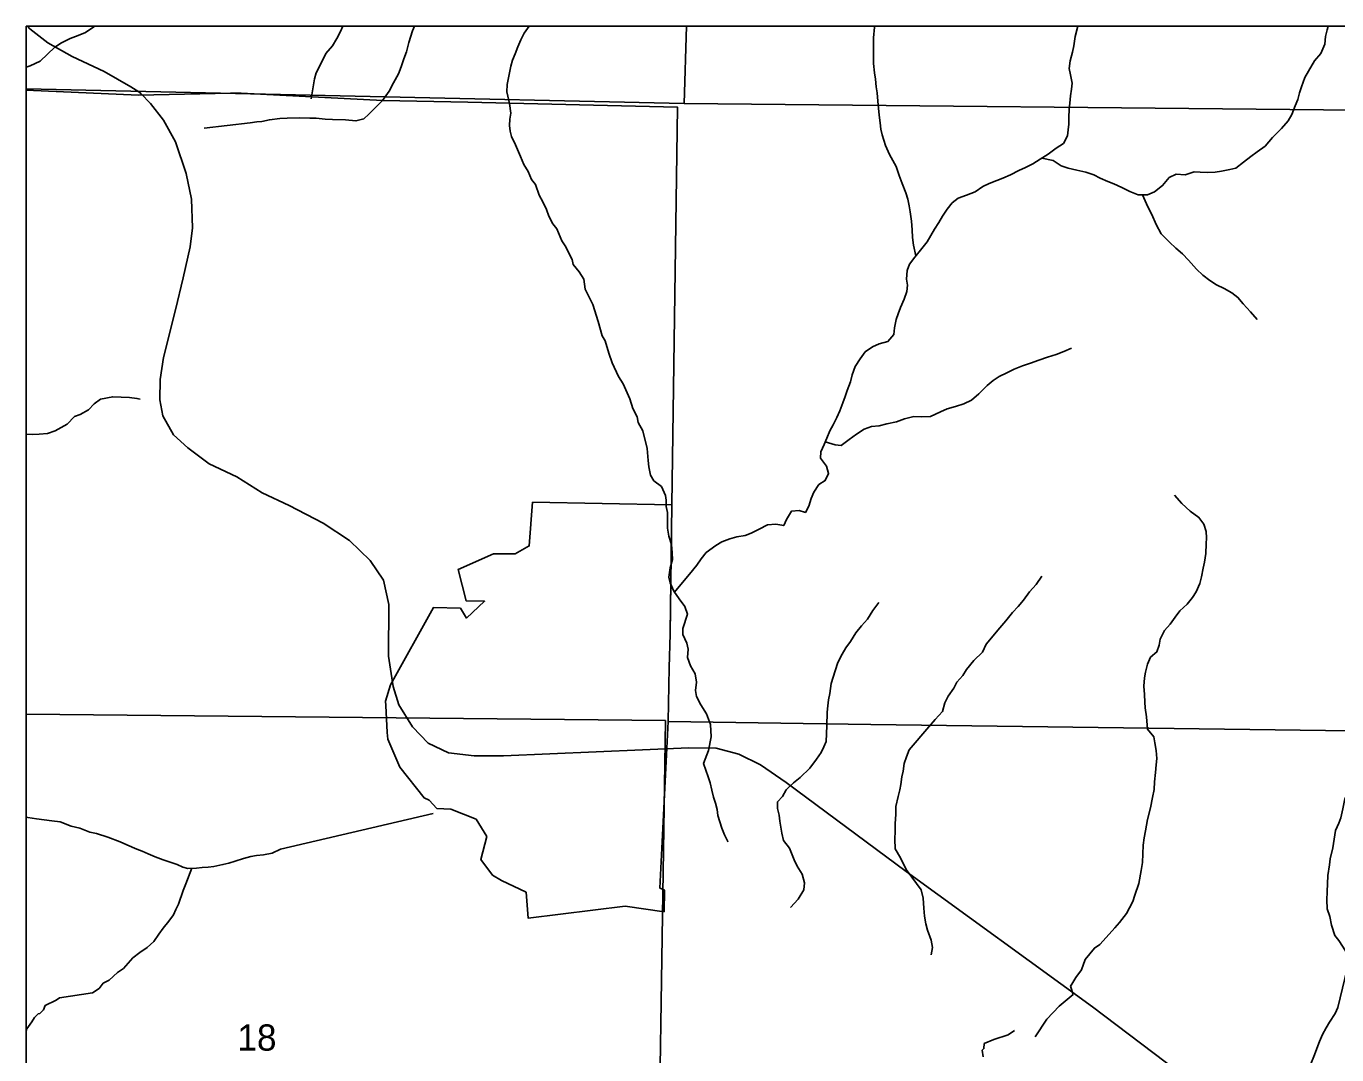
# Model space of a CAD drawing. Extents: x -10 to 158, y 8 to 33.
# Drawn here: x -9.791 to -7.704, y 21.18 to 22.818 of the extents above; entities that cross this region are included whole.
import ezdxf

# ---------------------------------------------------------------- set-up
doc = ezdxf.new("R2010")
doc.units = 0
for name, color, linetype in [('GM_X_Corporation', 7, 'Continuous'), ('GM_X_Minor_River', 7, 'Continuous'), ('GM_X_Rail_Line', 7, 'Continuous'), ('GM_X_Section_Text', 7, 'Continuous')]:
    doc.layers.add(name, color=color, linetype=linetype)

msp = doc.modelspace()

# ---------------------------------------------------------------- linework, layer by layer
at = {"layer": 'GM_X_Corporation'}
for points in [[(-2.9914, 22.8183), (-9.7914, 22.8183), (-9.7914, 22.7162), (-9.6128, 22.7087), (-9.4661, 22.7117), (-9.4489, 22.7118), (-9.2233, 22.7001), (-9.0882, 22.6971), (-8.7542, 22.6895), (-8.7629, 22.056), (-8.7657, 21.852), (-8.7657, 21.8499), (-8.7672, 21.7965), (-8.7692, 21.7106), (-8.4462, 21.7057), (-7.2795, 21.6904)], [(-3.5803, 22.8183), (-9.7914, 22.8183), (-9.7914, 22.7162), (-9.6128, 22.7087), (-9.4661, 22.7117), (-9.4489, 22.7118), (-9.2233, 22.7001), (-9.0882, 22.6971), (-8.7542, 22.6895), (-8.7629, 22.056), (-8.7657, 21.852), (-8.7657, 21.8499), (-8.7672, 21.7965), (-8.7692, 21.7106), (-8.4462, 21.7057), (-7.2795, 21.6904)], [(-7.2795, 21.6904), (-8.4462, 21.7057), (-8.7692, 21.7106), (-8.7672, 21.7965), (-8.7657, 21.8499), (-8.7657, 21.852), (-8.7629, 22.056), (-8.7542, 22.6895), (-9.0882, 22.6971), (-9.2233, 22.7001), (-9.4489, 22.7118), (-9.4661, 22.7117), (-9.6128, 22.7087), (-9.7914, 22.7162), (-9.7914, 16.0183)], [(-7.2795, 21.6904), (-8.4462, 21.7057), (-8.7692, 21.7106), (-8.7672, 21.7965), (-8.7657, 21.8499), (-8.7657, 21.852), (-8.7629, 22.056), (-8.7542, 22.6895), (-9.0882, 22.6971), (-9.2233, 22.7001), (-9.4489, 22.7118), (-9.4661, 22.7117), (-9.6128, 22.7087), (-9.7914, 22.7162), (-9.7914, 18.392)]]:
    msp.add_lwpolyline(points, dxfattribs=at)
for points in [[(-8.74, 22.8183), (-9.7914, 22.8183), (-9.7914, 22.7186), (-8.7435, 22.6953)], [(-7.6698, 22.8183), (-8.74, 22.8183), (-8.7435, 22.6953), (-7.6718, 22.6845)], [(-8.7692, 21.7106), (-8.7821, 21.4452), (-8.778, 21.4433), (-8.7748, 21.4417), (-8.7754, 21.4075), (-8.8374, 21.4166), (-8.9919, 21.3972), (-8.9953, 21.4385), (-9.0345, 21.4574), (-9.0486, 21.4657), (-9.0672, 21.4909), (-9.0579, 21.5274), (-9.0748, 21.555), (-9.1149, 21.5711), (-9.1372, 21.572), (-9.1497, 21.5854), (-9.1577, 21.5889), (-9.1961, 21.638), (-9.2157, 21.6826), (-9.2163, 21.6931), (-9.2187, 21.736), (-9.2193, 21.7432), (-9.2113, 21.7691), (-9.1426, 21.8922), (-9.0998, 21.8913), (-9.09, 21.8752), (-9.0615, 21.9022), (-9.0909, 21.9029), (-9.1033, 21.9528), (-9.0474, 21.9778), (-9.0124, 21.9778), (-8.9901, 21.9903), (-8.9848, 22.0598), (-8.7629, 22.056), (-8.7657, 21.8499), (-8.7672, 21.7965)], [(-9.7914, 21.7221), (-9.7914, 20.728), (-8.7888, 20.7117), (-8.7733, 21.712)]]:
    msp.add_lwpolyline(points, close=True, dxfattribs=at)
at = {"layer": 'GM_X_Minor_River'}
for points in [[(-9.6822, 22.8183), (-9.6835, 22.8173), (-9.6971, 22.8082), (-9.7089, 22.8035), (-9.7214, 22.7985), (-9.7354, 22.792), (-9.7456, 22.7847), (-9.7573, 22.774), (-9.769, 22.7626), (-9.7849, 22.7552), (-9.7914, 22.7532)], [(-9.3373, 22.7024), (-9.3351, 22.7187), (-9.3321, 22.7343), (-9.3295, 22.7438), (-9.3228, 22.7575), (-9.3142, 22.7746), (-9.3036, 22.7868), (-9.2965, 22.7986), (-9.2909, 22.8097), (-9.2872, 22.8183)], [(-9.2241, 22.6999), (-9.2132, 22.7146), (-9.2064, 22.7283), (-9.1985, 22.7424), (-9.1941, 22.7538), (-9.19, 22.7663), (-9.1855, 22.7777), (-9.1818, 22.7922), (-9.1762, 22.8112), (-9.1732, 22.8183)], [(-9.0217, 22.6953), (-9.026, 22.7139), (-9.0253, 22.7257), (-9.0224, 22.7413), (-9.0198, 22.7546), (-9.0168, 22.7641), (-9.0127, 22.7743), (-9.0082, 22.7854), (-9.0034, 22.7968), (-8.9985, 22.807), (-8.9903, 22.8183)], [(-8.7587, 21.9164), (-8.7459, 21.9322), (-8.735, 21.9455), (-8.7233, 21.9596), (-8.7166, 21.9695), (-8.7083, 21.9798), (-8.6932, 21.9909), (-8.6833, 21.9967), (-8.6708, 22.0017), (-8.6598, 22.0048), (-8.6462, 22.0071), (-8.6367, 22.0106), (-8.6238, 22.0168), (-8.6106, 22.0237), (-8.5973, 22.0249), (-8.5848, 22.0227), (-8.5807, 22.0322), (-8.5728, 22.0456), (-8.5606, 22.0468), (-8.5504, 22.0438), (-8.5451, 22.0537), (-8.5414, 22.0659), (-8.5369, 22.0757), (-8.529, 22.0879), (-8.5188, 22.0945), (-8.5136, 22.1059), (-8.517, 22.1176), (-8.5266, 22.1301), (-8.5259, 22.1403), (-8.5207, 22.1517), (-8.5162, 22.162), (-8.5113, 22.1734), (-8.5061, 22.1833), (-8.5005, 22.1951), (-8.4956, 22.2054), (-8.4908, 22.2183), (-8.487, 22.2285), (-8.4837, 22.2381), (-8.4788, 22.2517), (-8.4759, 22.2628), (-8.471, 22.2764), (-8.4631, 22.2886), (-8.4552, 22.2993), (-8.4435, 22.3077), (-8.4329, 22.312), (-8.4189, 22.3158), (-8.4098, 22.3273), (-8.4084, 22.3375), (-8.4058, 22.3508), (-8.4028, 22.3603), (-8.3991, 22.3702), (-8.3931, 22.3835), (-8.389, 22.3957), (-8.388, 22.4059), (-8.3895, 22.4154), (-8.3881, 22.4291), (-8.3848, 22.439), (-8.3761, 22.4504), (-8.3648, 22.4641), (-8.3565, 22.4748), (-8.3505, 22.4847), (-8.3449, 22.495), (-8.3377, 22.5056), (-8.3321, 22.5159), (-8.3246, 22.527), (-8.3167, 22.5369), (-8.3069, 22.5445), (-8.2936, 22.5492), (-8.2803, 22.5546), (-8.2679, 22.563), (-8.258, 22.5676), (-8.2455, 22.5726), (-8.2361, 22.5761), (-8.2236, 22.5815), (-8.2103, 22.5884), (-8.1997, 22.593), (-8.1884, 22.5992), (-8.1763, 22.6065), (-8.1638, 22.6145), (-8.1509, 22.6241), (-8.1396, 22.6317), (-8.1332, 22.6435), (-8.1318, 22.653), (-8.1307, 22.6625), (-8.1311, 22.6735), (-8.1301, 22.6856), (-8.1294, 22.6955), (-8.1283, 22.7073), (-8.1265, 22.7179), (-8.1254, 22.7278), (-8.1282, 22.741), (-8.1301, 22.7509), (-8.1287, 22.7634), (-8.125, 22.7767), (-8.1228, 22.7873), (-8.121, 22.8021), (-8.1173, 22.8162), (-8.1166, 22.8183)], [(-8.3743, 22.4526), (-8.3785, 22.4693), (-8.3801, 22.4819), (-8.3806, 22.494), (-8.3814, 22.5076), (-8.3834, 22.5224), (-8.3854, 22.5323), (-8.3873, 22.5425), (-8.3904, 22.5527), (-8.3962, 22.5678), (-8.4009, 22.5807), (-8.4059, 22.5947), (-8.4163, 22.614), (-8.4228, 22.6284), (-8.4283, 22.645), (-8.4302, 22.6545), (-8.4314, 22.6643), (-8.433, 22.6768), (-8.4342, 22.6878), (-8.4351, 22.6988), (-8.4359, 22.7121), (-8.4375, 22.7216), (-8.4387, 22.7341), (-8.4403, 22.7439), (-8.4419, 22.7587), (-8.4422, 22.7997), (-8.4404, 22.8168), (-8.4402, 22.8183)], [(-8.1738, 22.608), (-8.1557, 22.6043), (-8.1432, 22.596), (-8.1317, 22.5923), (-8.1181, 22.589), (-8.1036, 22.5857), (-8.091, 22.5816), (-8.0808, 22.576), (-8.069, 22.5711), (-8.0591, 22.5674), (-8.0465, 22.5614), (-8.0335, 22.5547), (-8.0202, 22.5494), (-8.0058, 22.5495), (-7.9944, 22.5542), (-7.9816, 22.5645), (-7.971, 22.5774), (-7.9597, 22.5828), (-7.9456, 22.5814), (-7.9312, 22.5864), (-7.9217, 22.5857), (-7.9103, 22.585), (-7.8978, 22.5859), (-7.8876, 22.5875), (-7.8747, 22.5898), (-7.8648, 22.5922), (-7.8527, 22.6017), (-7.841, 22.6105), (-7.8308, 22.6182), (-7.8183, 22.6274), (-7.8063, 22.6411), (-7.792, 22.6556), (-7.7818, 22.6674), (-7.7758, 22.6777), (-7.7702, 22.6914), (-7.7664, 22.7017), (-7.7635, 22.7123), (-7.7601, 22.7218), (-7.7549, 22.7366), (-7.7493, 22.7469), (-7.7395, 22.7633), (-7.7293, 22.7747), (-7.7234, 22.7899), (-7.7223, 22.8021), (-7.7197, 22.8123), (-7.718, 22.8183)], [(-9.2241, 22.6999), (-9.2457, 22.678), (-9.2539, 22.6707), (-9.2664, 22.6675), (-9.2828, 22.6691), (-9.3034, 22.6696), (-9.3152, 22.6701), (-9.3296, 22.6718), (-9.3395, 22.672), (-9.3555, 22.6722), (-9.3756, 22.6719), (-9.3874, 22.6713), (-9.4041, 22.6692), (-9.4159, 22.6667), (-9.4242, 22.6658), (-9.4345, 22.6645), (-9.5079, 22.656)], [(-8.773, 22.0706), (-8.7796, 22.0848), (-8.7919, 22.0941), (-8.7969, 22.1032), (-8.7998, 22.1164), (-8.8007, 22.1263), (-8.8025, 22.1456), (-8.8094, 22.1736), (-8.8168, 22.1868), (-8.8185, 22.1959), (-8.8255, 22.209), (-8.8303, 22.2249), (-8.8405, 22.2487), (-8.8479, 22.2603), (-8.8581, 22.2822), (-8.8637, 22.2973), (-8.8693, 22.317), (-8.874, 22.3252), (-8.8804, 22.3479), (-8.8891, 22.3748), (-8.9013, 22.3996), (-8.9034, 22.4155), (-8.9108, 22.4268), (-8.9205, 22.4384), (-8.9221, 22.4468), (-8.9331, 22.4682), (-8.9382, 22.4765), (-8.9464, 22.4954), (-8.9526, 22.5036), (-8.9589, 22.5157), (-8.9629, 22.5263), (-8.9684, 22.5387), (-8.9742, 22.5489), (-8.9802, 22.5659), (-8.9864, 22.5741), (-8.9919, 22.5869), (-8.9989, 22.5982), (-9.004, 22.6107), (-9.0119, 22.6292), (-9.0186, 22.6427), (-9.0206, 22.6511), (-9.0215, 22.6602), (-9.0212, 22.6704), (-9.0195, 22.6799), (-9.0217, 22.6953)], [(-8.0134, 22.5495), (-8.0049, 22.5306), (-7.9987, 22.5181), (-7.9918, 22.5022), (-7.9837, 22.4875), (-7.9704, 22.4743), (-7.9604, 22.4649), (-7.9497, 22.4555), (-7.9402, 22.4453), (-7.9275, 22.4313), (-7.9176, 22.4219), (-7.9062, 22.4132), (-7.8959, 22.4061), (-7.8837, 22.4005), (-7.8711, 22.3934), (-7.8616, 22.3862), (-7.8531, 22.376), (-7.8413, 22.3632), (-7.831, 22.3512)], [(-8.5189, 22.1559), (-8.5032, 22.1511), (-8.4937, 22.1504), (-8.4809, 22.1596), (-8.4688, 22.1684), (-8.4567, 22.1764), (-8.4453, 22.1803), (-8.4332, 22.1815), (-8.4207, 22.1846), (-8.4055, 22.1881), (-8.3926, 22.1928), (-8.3775, 22.1963), (-8.3657, 22.196), (-8.3513, 22.1964), (-8.335, 22.2041), (-8.3248, 22.2087), (-8.3115, 22.2122), (-8.2979, 22.2165), (-8.2857, 22.2227), (-8.274, 22.2326), (-8.2612, 22.246), (-8.2514, 22.2536), (-8.2416, 22.2601), (-8.2298, 22.2659), (-8.2177, 22.272), (-8.2045, 22.277), (-8.192, 22.2817), (-8.1787, 22.2863), (-8.1647, 22.291), (-8.1511, 22.2952), (-8.1389, 22.3002), (-8.1264, 22.3056)], [(-9.61, 22.2242), (-9.6151, 22.2252), (-9.6269, 22.2269), (-9.6535, 22.228), (-9.6729, 22.2239), (-9.683, 22.2169), (-9.6924, 22.2069), (-9.7052, 22.1999), (-9.7147, 22.1967), (-9.7263, 22.1844), (-9.7451, 22.1735), (-9.7576, 22.1695), (-9.7705, 22.1681), (-9.7812, 22.168), (-9.7914, 22.1682)], [(-8.7016, 21.7056), (-8.7081, 21.723), (-8.7169, 21.737), (-8.7238, 21.7502), (-8.7254, 21.7601), (-8.7236, 21.773), (-8.726, 21.7866), (-8.7333, 21.7995), (-8.7383, 21.8123), (-8.7372, 21.826), (-8.7392, 21.8355), (-8.7454, 21.8491), (-8.7458, 21.8586), (-8.7384, 21.8814), (-8.7423, 21.8939), (-8.7514, 21.9059), (-8.7599, 21.918), (-8.766, 21.9313), (-8.768, 21.9407), (-8.7658, 21.9552), (-8.7621, 21.9688), (-8.7626, 21.9795), (-8.7638, 21.9927), (-8.7677, 22.0056), (-8.77, 22.0185), (-8.7702, 22.0435), (-8.7722, 22.053), (-8.7722, 22.0632), (-8.773, 22.0706)], [(-8.0055, 21.6981), (-8.0071, 21.7181), (-8.0091, 21.7321), (-8.0096, 21.7416), (-8.0104, 21.7534), (-8.0113, 21.7666), (-8.0102, 21.7799), (-8.0088, 21.7894), (-8.0054, 21.802), (-8.0006, 21.813), (-7.9907, 21.8214), (-7.987, 21.832), (-7.9856, 21.8419), (-7.9784, 21.8556), (-7.9694, 21.8655), (-7.9615, 21.8766), (-7.954, 21.8869), (-7.9426, 21.8976), (-7.934, 21.9079), (-7.9283, 21.9174), (-7.9223, 21.9303), (-7.9198, 21.9409), (-7.9168, 21.9546), (-7.915, 21.9645), (-7.9128, 21.9782), (-7.9121, 21.9937), (-7.9114, 22.0032), (-7.9123, 22.0131), (-7.9158, 22.0252), (-7.9238, 22.0357), (-7.9379, 22.0455), (-7.9509, 22.0579), (-7.9624, 22.0711)], [(-8.3541, 21.7019), (-8.3435, 21.7137), (-8.3322, 21.7266), (-8.3281, 21.7403), (-8.3229, 21.751), (-8.3142, 21.7635), (-8.309, 21.7734), (-8.2999, 21.7837), (-8.2936, 21.7936), (-8.2823, 21.8077), (-8.2683, 21.8211), (-8.2623, 21.834), (-8.254, 21.844), (-8.2438, 21.8562), (-8.231, 21.871), (-8.2205, 21.884), (-8.2114, 21.8939), (-8.2032, 21.9038), (-8.1934, 21.9172), (-8.1828, 21.929), (-8.1738, 21.942)], [(-8.5163, 21.7036), (-8.516, 21.7254), (-8.5149, 21.7353), (-8.5135, 21.7452), (-8.5116, 21.7554), (-8.5094, 21.771), (-8.5061, 21.7812), (-8.5031, 21.7915), (-8.4987, 21.8048), (-8.4919, 21.8177), (-8.4859, 21.828), (-8.4788, 21.8379), (-8.4701, 21.8516), (-8.4611, 21.8631), (-8.4517, 21.8738), (-8.443, 21.8875), (-8.4336, 21.9004)], [(-8.7016, 21.7056), (-8.7004, 21.6859), (-8.705, 21.6645), (-8.7127, 21.6439), (-8.7091, 21.6331), (-8.7055, 21.6226), (-8.7022, 21.6126), (-8.6997, 21.6014), (-8.6969, 21.5902), (-8.6936, 21.5802), (-8.6911, 21.5702), (-8.6897, 21.5606), (-8.6868, 21.5505), (-8.6835, 21.5405), (-8.6795, 21.53), (-8.6739, 21.5195), (-8.6732, 21.5188)], [(-8.5742, 21.4141), (-8.5619, 21.4275), (-8.553, 21.4421), (-8.5517, 21.4535), (-8.5557, 21.4675), (-8.5635, 21.4803), (-8.5682, 21.4901), (-8.576, 21.5085), (-8.5854, 21.5209), (-8.5882, 21.5327), (-8.5911, 21.552), (-8.592, 21.5615), (-8.5948, 21.5717), (-8.595, 21.5823), (-8.5871, 21.5911), (-8.5808, 21.6015), (-8.5696, 21.6127), (-8.5587, 21.6212), (-8.5433, 21.6362), (-8.5329, 21.6508), (-8.5251, 21.6612), (-8.521, 21.6704), (-8.5173, 21.6788), (-8.5163, 21.7036)], [(-8.3503, 21.3387), (-8.3482, 21.3503), (-8.3499, 21.3624), (-8.3559, 21.3779), (-8.3587, 21.3884), (-8.3608, 21.4006), (-8.3617, 21.4131), (-8.3631, 21.429), (-8.3659, 21.4426), (-8.3807, 21.4625), (-8.39, 21.4749), (-8.399, 21.4934), (-8.4076, 21.5077), (-8.4082, 21.5229), (-8.4076, 21.5358), (-8.4074, 21.5475), (-8.4065, 21.5627), (-8.4063, 21.5749), (-8.4027, 21.5913), (-8.4002, 21.6019), (-8.3984, 21.6103), (-8.3967, 21.6225), (-8.3946, 21.6313), (-8.3929, 21.6438), (-8.3892, 21.6545), (-8.3852, 21.6652), (-8.3541, 21.7019)], [(-8.1283, 21.2891), (-8.1261, 21.2921), (-8.1198, 21.3025), (-8.1108, 21.3147), (-8.1046, 21.3315), (-8.0901, 21.3496), (-8.0814, 21.355), (-8.0664, 21.3716), (-8.0574, 21.3816), (-8.05, 21.3905), (-8.0391, 21.4047), (-8.0343, 21.4135), (-8.0292, 21.4238), (-8.0259, 21.4341), (-8.0193, 21.4524), (-8.0158, 21.473), (-8.0133, 21.4859), (-8.0132, 21.4996), (-8.0126, 21.5133), (-8.0109, 21.5254), (-8.0088, 21.5361), (-8.007, 21.5456), (-8.0056, 21.5544), (-8.0006, 21.5731), (-7.9974, 21.5894), (-7.9949, 21.6024), (-7.9943, 21.6142), (-7.993, 21.6294), (-7.9917, 21.6415), (-7.9907, 21.6518), (-7.992, 21.6643), (-7.9941, 21.6768), (-7.9954, 21.6859), (-8.0055, 21.6981)], [(-7.6877, 21.3166), (-7.6874, 21.3219), (-7.6868, 21.3348), (-7.6904, 21.3454), (-7.7009, 21.3616), (-7.7071, 21.3698), (-7.7123, 21.3861), (-7.7151, 21.3997), (-7.7195, 21.4122), (-7.7201, 21.4262), (-7.7195, 21.4391), (-7.7184, 21.4653), (-7.7159, 21.4821), (-7.7146, 21.492), (-7.7106, 21.5091), (-7.7061, 21.5369), (-7.7009, 21.5484), (-7.6977, 21.5571), (-7.6944, 21.5712), (-7.6912, 21.5872), (-7.6831, 21.6025), (-7.6758, 21.6205), (-7.6664, 21.632)], [(-9.1433, 21.5641), (-9.3863, 21.5069), (-9.3999, 21.501), (-9.4135, 21.4981), (-9.4245, 21.4968), (-9.4337, 21.4956), (-9.4454, 21.4923), (-9.4586, 21.488), (-9.4689, 21.4848), (-9.478, 21.4827), (-9.4927, 21.4798), (-9.5015, 21.4786), (-9.511, 21.4777), (-9.5201, 21.4768), (-9.5338, 21.4766), (-9.5421, 21.4783), (-9.551, 21.4828), (-9.5636, 21.4871), (-9.5731, 21.4904), (-9.5861, 21.4948), (-9.5972, 21.4995), (-9.6068, 21.5039), (-9.6152, 21.5072), (-9.6313, 21.5138), (-9.6416, 21.519), (-9.6615, 21.5263), (-9.6794, 21.5321), (-9.6901, 21.5342), (-9.7058, 21.5408), (-9.7199, 21.5436), (-9.7375, 21.5506), (-9.7505, 21.5523), (-9.763, 21.554), (-9.7752, 21.5557), (-9.7889, 21.5577), (-9.7914, 21.5582)], [(-9.5277, 21.4767), (-9.5372, 21.4518), (-9.5416, 21.4415), (-9.5489, 21.4194), (-9.5529, 21.411), (-9.5566, 21.4026), (-9.5641, 21.3922), (-9.573, 21.3811), (-9.5801, 21.3718), (-9.5879, 21.36), (-9.5988, 21.3507), (-9.6105, 21.3425), (-9.6214, 21.334), (-9.6364, 21.3171), (-9.6461, 21.3105), (-9.6593, 21.2985), (-9.6687, 21.2934), (-9.6754, 21.285), (-9.6856, 21.2784), (-9.7385, 21.2703)], [(-7.8657, 21.0318), (-7.8496, 21.0356), (-7.838, 21.0423), (-7.8271, 21.0477), (-7.8199, 21.0517), (-7.8128, 21.0567), (-7.8046, 21.0644), (-7.7971, 21.0737), (-7.7912, 21.0836), (-7.7843, 21.0963), (-7.7758, 21.1112), (-7.7677, 21.1247), (-7.7592, 21.1385), (-7.7514, 21.1523), (-7.7452, 21.1653), (-7.7405, 21.1768), (-7.7318, 21.2005), (-7.7267, 21.2119), (-7.7211, 21.2223), (-7.7156, 21.2315), (-7.7067, 21.2453), (-7.7023, 21.2549), (-7.6877, 21.3166)], [(-9.7914, 21.2165), (-9.7904, 21.2208), (-9.7826, 21.232), (-9.7782, 21.2389), (-9.7726, 21.2447), (-9.7696, 21.2455), (-9.764, 21.2513), (-9.7611, 21.2581), (-9.7437, 21.2668), (-9.7385, 21.2703)], [(-8.1846, 21.2081), (-8.1658, 21.2365), (-8.1461, 21.2571), (-8.1242, 21.2758), (-8.1283, 21.2891)], [(-8.2674, 21.1761), (-8.2678, 21.1802), (-8.2683, 21.1833), (-8.2687, 21.1867), (-8.2661, 21.1894), (-8.2655, 21.1974), (-8.2504, 21.2041), (-8.2274, 21.2113), (-8.2174, 21.2182)]]:
    msp.add_lwpolyline(points, dxfattribs=at)
at = {"layer": 'GM_X_Rail_Line'}
for points in [[(-9.7893, 22.8183), (-9.7855, 22.8139), (-9.7567, 22.7917), (-9.7183, 22.7703), (-9.6674, 22.746), (-9.6246, 22.7216), (-9.6122, 22.7135)], [(-9.6122, 22.7135), (-9.6087, 22.7112), (-9.5932, 22.695), (-9.5727, 22.6684), (-9.5538, 22.634), (-9.5366, 22.5835), (-9.5283, 22.5426), (-9.5263, 22.4971), (-9.5301, 22.4669), (-9.5412, 22.4174), (-9.5537, 22.3664), (-9.5729, 22.2904), (-9.5781, 22.2557), (-9.5788, 22.2232), (-9.5737, 22.1974), (-9.5567, 22.1674), (-9.5339, 22.1464), (-9.4998, 22.1213), (-9.456, 22.1006), (-9.4154, 22.0749), (-9.3725, 22.0549), (-9.3184, 22.0267), (-9.2766, 21.9988), (-9.2435, 21.9673), (-9.2223, 21.9356), (-9.2138, 21.8968), (-9.2143, 21.8145), (-9.2072, 21.7665), (-9.1982, 21.7371), (-9.176, 21.7023), (-9.151, 21.676), (-9.119, 21.6606), (-9.0777, 21.6561), (-9.0312, 21.6561), (-8.736, 21.6687), (-8.6925, 21.668), (-8.6563, 21.6584), (-8.6222, 21.6417), (-8.581, 21.6135), (-8.3899, 21.4715), (-8.0932, 21.2559), (-7.9382, 21.1385)]]:
    msp.add_lwpolyline(points, dxfattribs=at)

# ---------------------------------------------------------------- texts
at = {"layer": 'GM_X_Section_Text'}
msp.add_text('18', height=0.04186, rotation=0, dxfattribs=at).set_placement((-9.455, 21.1861))

doc.saveas('drawing.dxf')
